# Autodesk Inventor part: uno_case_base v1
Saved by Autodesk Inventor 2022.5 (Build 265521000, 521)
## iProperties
Created: 2024-05
Part Number: uno_case_base v1
Material: Generic
Document SubType Name: Modeling
Designer: AdminForWorker
Density: 1 g/cm^3
Appearance: Default
Title: uno_case_base v1
Author: AdminForWorker
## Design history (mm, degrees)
feature "MeshBody1"
body "Solid1"
